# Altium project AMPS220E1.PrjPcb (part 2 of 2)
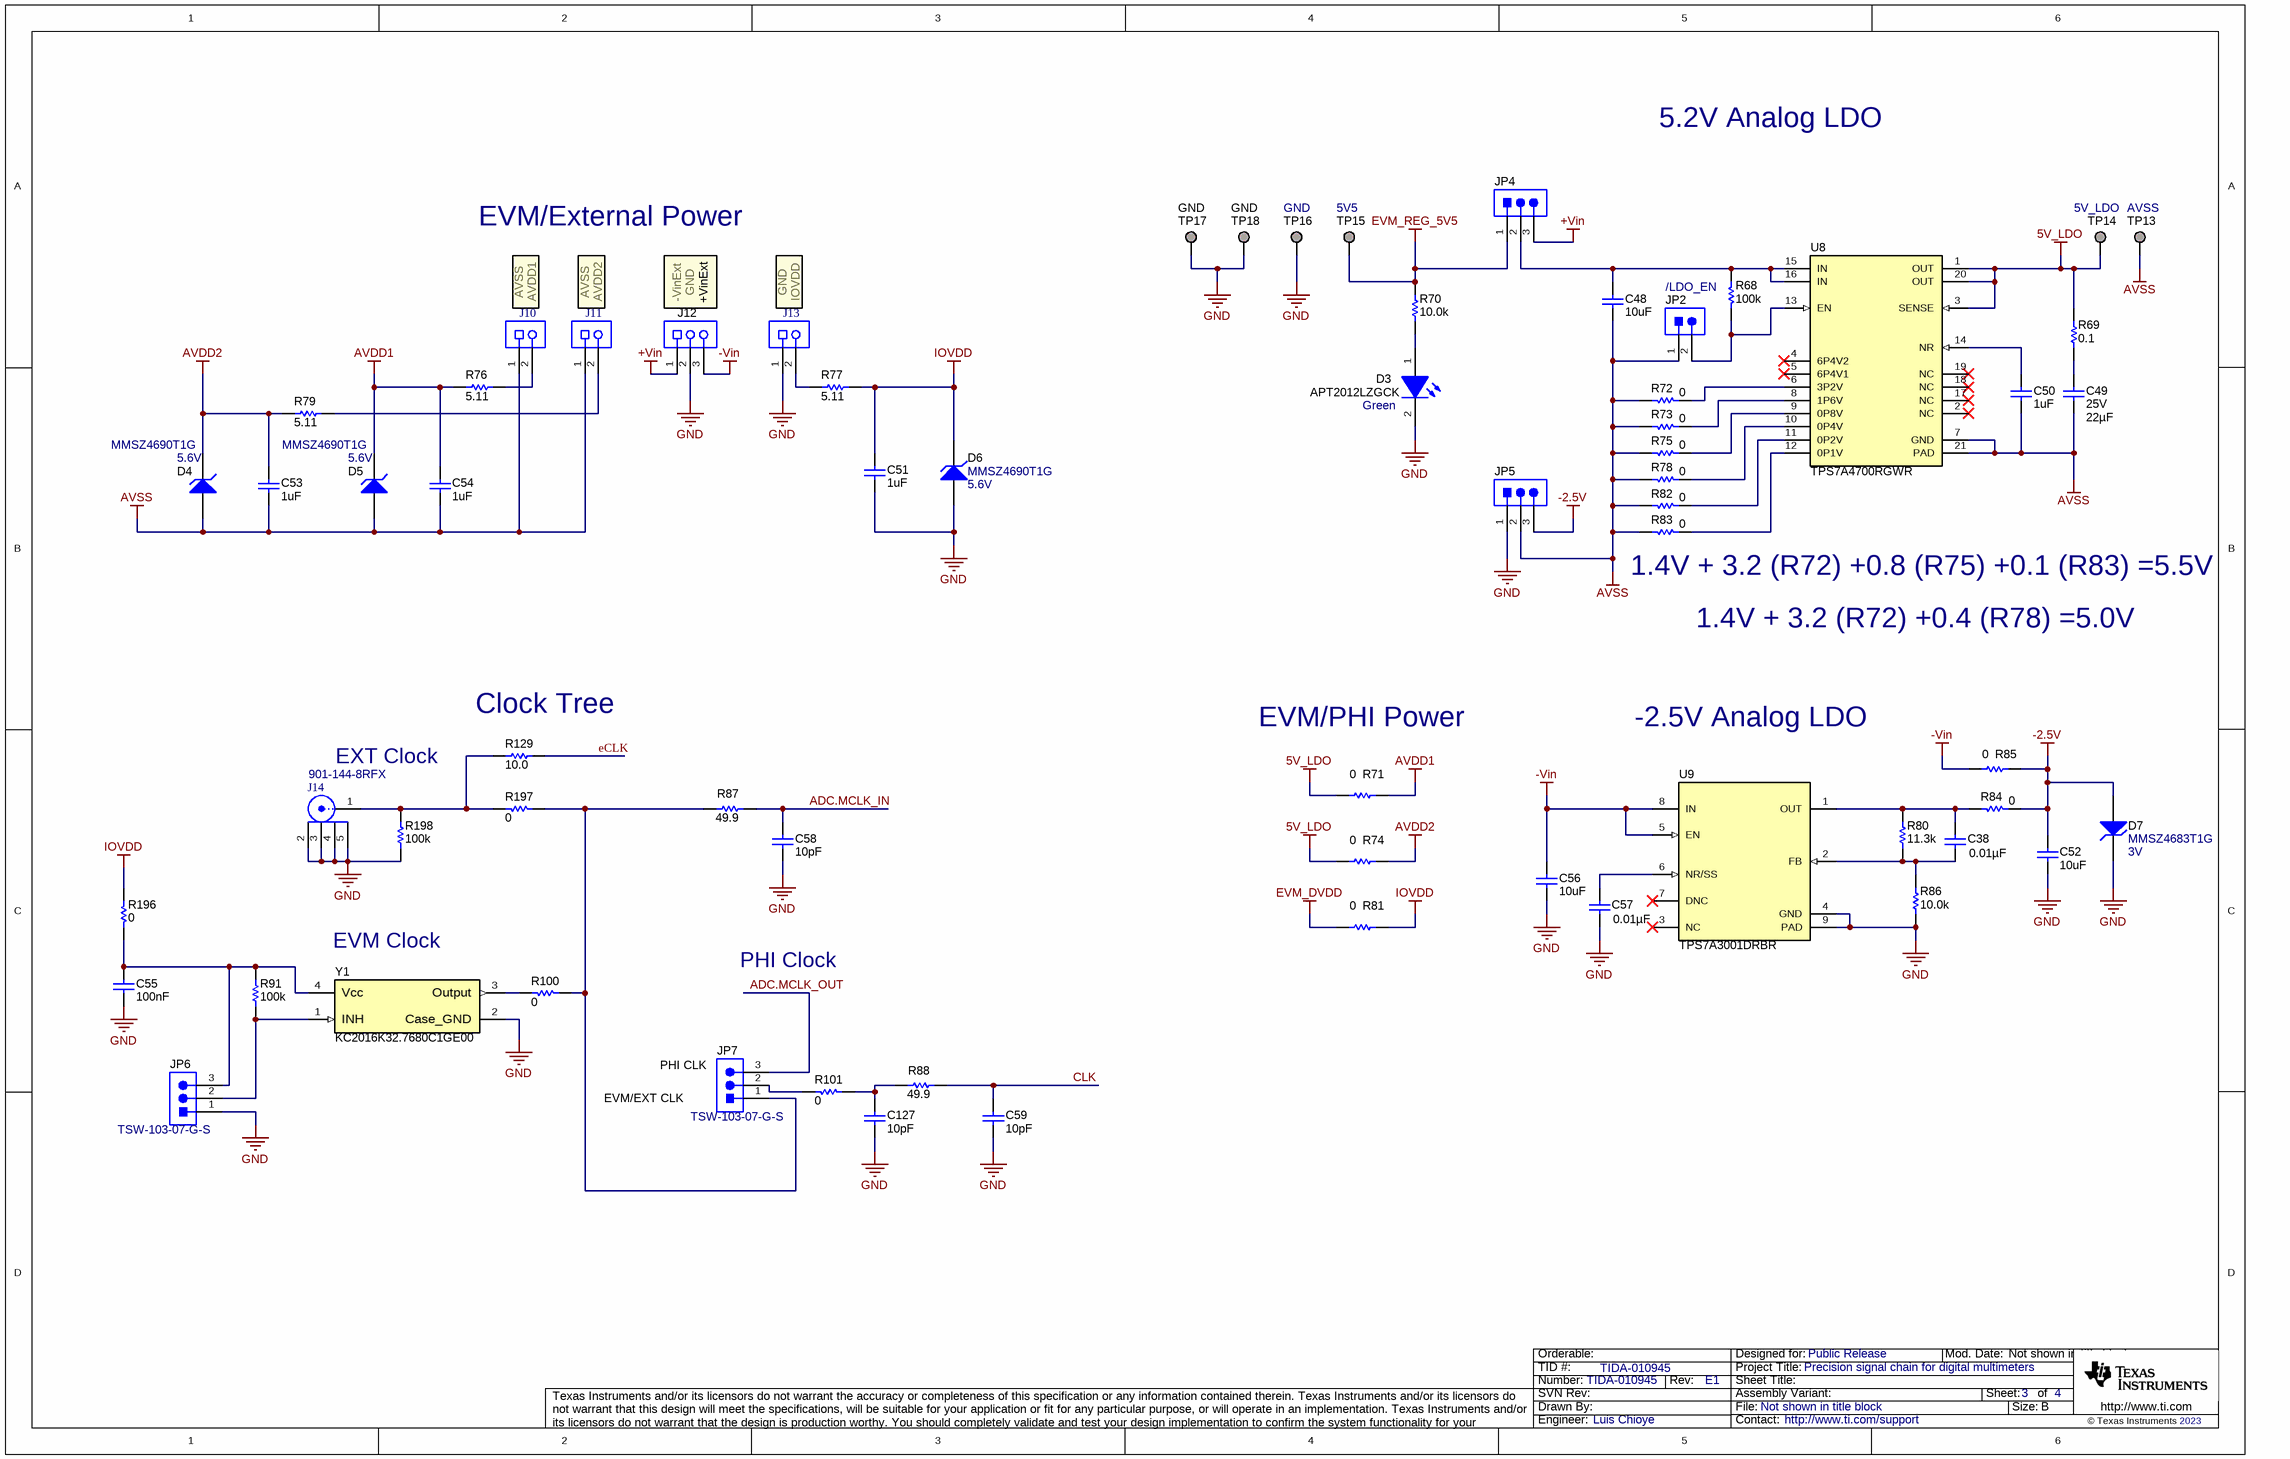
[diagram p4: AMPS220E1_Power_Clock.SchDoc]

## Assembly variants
001: not fitted C33 C58 C59 C60 C63 C127 FID1 FID2 FID3 J9 JP2 R17 R23 R30 R32 R33 R35 R42 R45 R47 R52 R53 R54 R56 R60 R67 R73 R75 R82 R83 R85 R89 R93 R95 R96 R97 R129 R130 TP1 TP2 TP3 TP4 TP5 TP6 TP7 TP8 TP9 TP10 TP11 TP12 TP13 TP14 TP15 TP16
002: not fitted C33 C58 C59 C60 C63 C127 FID1 FID2 FID3 J9 JP2 R17 R23 R30 R32 R33 R35 R42 R45 R47 R52 R53 R54 R56 R60 R67 R73 R75 R82 R83 R85 R89 R93 R95 R96 R97 R129 R130 TP1 TP2 TP3 TP4 TP5 TP6 TP7 TP8 TP9 TP10 TP11 TP12 TP13 TP14 TP15 TP16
